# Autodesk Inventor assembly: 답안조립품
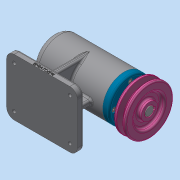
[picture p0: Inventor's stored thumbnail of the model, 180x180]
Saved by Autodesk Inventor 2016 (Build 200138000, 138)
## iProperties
Created: 2020-10
Part Number: 답안조립품
Document SubType Name: Assembly
Designer: User
Author: User
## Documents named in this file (12)
- C:\Users\88ljm\Desktop\701004V1001 박찬석\답안조립품.iam
- C:\Users\88ljm\Desktop\701004V1001 박찬석\본체.ipt
- C:\Users\88ljm\Desktop\701004V1001 박찬석\커버.ipt
- C:\Users\88ljm\Desktop\701004V1001 박찬석\축.ipt
- C:\Users\88ljm\Desktop\701004V1001 박찬석\베어링 6004.ipt
- C:\Users\88ljm\Desktop\701004V1001 박찬석\오일 실.ipt
- C:\Users\88ljm\Desktop\701004V1001 박찬석\어댑터슬리브.ipt
- C:\Users\88ljm\Desktop\701004V1001 박찬석\베어링 51202.ipt
- C:\Users\88ljm\Desktop\701004V1001 박찬석\볼트 M4.ipt
- C:\Users\88ljm\Desktop\701004V1001 박찬석\키 5 x 5 x 16.ipt
- C:\Users\88ljm\Desktop\701004V1001 박찬석\V벨트풀리.ipt
- C:\Users\88ljm\Desktop\701004V1001 박찬석\멈춤나사 M3.ipt
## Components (1 placed, 1 different names)
1. V벨트풀리:1 — 플러쉬:1
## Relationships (1: Flush 1)
- 플러쉬:1 [Flush]: V벨트풀리:1
